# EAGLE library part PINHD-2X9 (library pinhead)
PIN HEADER
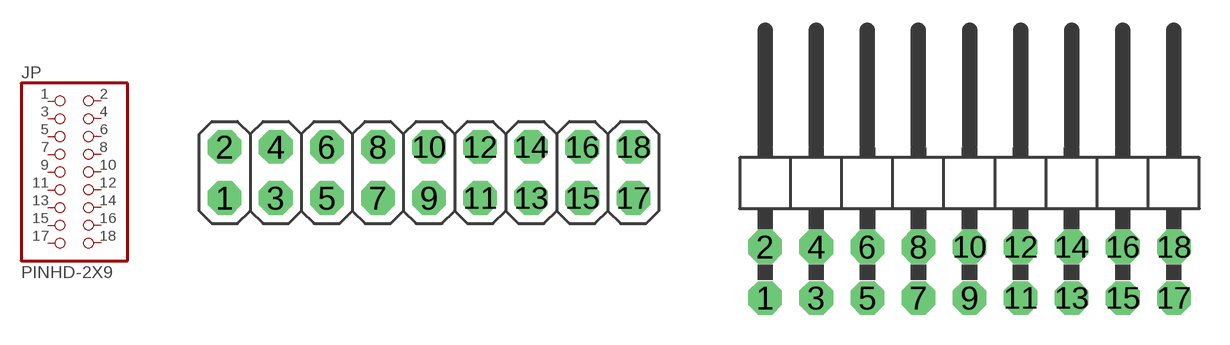
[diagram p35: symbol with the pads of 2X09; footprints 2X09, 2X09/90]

Designator prefix JP

## PINHD-2X9  [2X09]
1  1  pas
2  2  pas
3  3  pas
4  4  pas
5  5  pas
6  6  pas
7  7  pas
8  8  pas
9  9  pas
10  10  pas
11  11  pas
12  12  pas
13  13  pas
14  14  pas
15  15  pas
16  16  pas
17  17  pas
18  18  pas

## PINHD-2X9/90  [2X09/90]
Pads as for 2X09

## Footprint 2X09 (pad centres in mm)
PIN HEADER
drill 1.016 pad 1.67 octagon: 1 -10.16,-1.27; 2 -10.16,1.27; 3 -7.62,-1.27; 4 -7.62,1.27; 5 -5.08,-1.27; 6 -5.08,1.27; 7 -2.54,-1.27; 8 -2.54,1.27; 9 0,-1.27; 10 0,1.27; 11 2.54,-1.27; 12 2.54,1.27; 13 5.08,-1.27; 14 5.08,1.27; 15 7.62,-1.27; 16 7.62,1.27; 17 10.16,-1.27; 18 10.16,1.27

## Footprint 2X09/90 (pad centres in mm)
PIN HEADER
drill 1.016 pad 1.67 octagon: 1 -10.16,-6.35; 2 -10.16,-3.81; 3 -7.62,-6.35; 4 -7.62,-3.81; 5 -5.08,-6.35; 6 -5.08,-3.81; 7 -2.54,-6.35; 8 -2.54,-3.81; 9 0,-6.35; 10 0,-3.81; 11 2.54,-6.35; 12 2.54,-3.81; 13 5.08,-6.35; 14 5.08,-3.81; 15 7.62,-6.35; 16 7.62,-3.81; 17 10.16,-6.35; 18 10.16,-3.81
